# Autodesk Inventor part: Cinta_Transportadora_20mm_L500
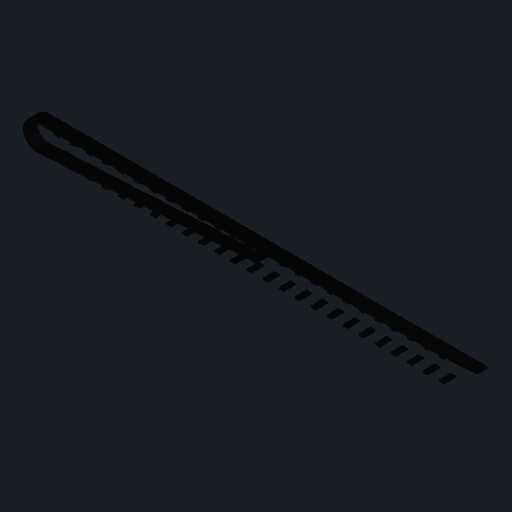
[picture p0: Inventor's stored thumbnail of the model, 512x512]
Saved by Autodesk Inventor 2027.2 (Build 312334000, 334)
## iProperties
Part Number: Cinta_Transportadora_20mm_L500
Material: Genérico
Document SubType Name: Modelado
Designer: Usuario
Appearance: Por defecto
Author: Usuario
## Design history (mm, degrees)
sketch "Boceto1"
  geometry: L1 (-220, 14)-(220, 14); L2 (220, 14)-(-220, -14); A1 r 14 centre (220, 0) between (220, -14) and (220, 14); A2 r 14 centre (-220, 0) between (-220, 14) and (-220, -14)
  constraints: 4 end point, 4 point on circle, 2 centre point
extrude "Extrusión1" new body sketch "Boceto1" stored distance "d0" = 12; taper "d1" = 0 deg
sketch "Boceto2"
  geometry: L1 (-220, 11.5)-(220, 11.5); L2 (220, 11.5)-(-220, -11.5); A1 r 11.5 centre (220, 0) between (220, -11.5) and (220, 11.5); A2 r 11.5 centre (-220, 0) between (-220, 11.5) and (-220, -11.5)
  constraints: 4 end point, 4 point on circle, 2 centre point
extrude "Extrusión2" cut sketch "Boceto2" stored distance "d2" = 12; taper "d3" = 0 deg
sketch "Boceto3"
  geometry: L1 (-202.5, -11.5)-(-197.5, -11.5); L2 (-197.5, -11.5)-(-197.5, -9.7); L3 (-197.5, -9.7)-(-202.5, -9.7); L4 (-202.5, -9.7)-(-202.5, -11.5); L5 (-202.5, 9.7)-(-197.5, 9.7); L6 (-197.5, 9.7)-(-197.5, 11.5); L7 (-197.5, 11.5)-(-202.5, 11.5); L8 (-202.5, 11.5)-(-202.5, 9.7); L9 (-186.5, -11.5)-(-181.5, -11.5); L10 (-181.5, -11.5)-(-181.5, -9.7); L11 (-181.5, -9.7)-(-186.5, -9.7); L12 (-186.5, -9.7)-(-186.5, -11.5); L13 (-186.5, 9.7)-(-181.5, 9.7); L14 (-181.5, 9.7)-(-181.5, 11.5); L15 (-181.5, 11.5)-(-186.5, 11.5); L16 (-186.5, 11.5)-(-186.5, 9.7); L17 (-170.5, -11.5)-(-165.5, -11.5); L18 (-165.5, -11.5)-(-165.5, -9.7); L19 (-165.5, -9.7)-(-170.5, -9.7); L20 (-170.5, -9.7)-(-170.5, -11.5); L21 (-170.5, 9.7)-(-165.5, 9.7); L22 (-165.5, 9.7)-(-165.5, 11.5); L23 (-165.5, 11.5)-(-170.5, 11.5); L24 (-170.5, 11.5)-(-170.5, 9.7); L25 (-154.5, -11.5)-(-149.5, -11.5); L26 (-149.5, -11.5)-(-149.5, -9.7); L27 (-149.5, -9.7)-(-154.5, -9.7); L28 (-154.5, -9.7)-(-154.5, -11.5); L29 (-154.5, 9.7)-(-149.5, 9.7); L30 (-149.5, 9.7)-(-149.5, 11.5); L31 (-149.5, 11.5)-(-154.5, 11.5); L32 (-154.5, 11.5)-(-154.5, 9.7); L33 (-138.5, -11.5)-(-133.5, -11.5); L34 (-133.5, -11.5)-(-133.5, -9.7); L35 (-133.5, -9.7)-(-138.5, -9.7); L36 (-138.5, -9.7)-(-138.5, -11.5); L37 (-138.5, 9.7)-(-133.5, 9.7); L38 (-133.5, 9.7)-(-133.5, 11.5); L39 (-133.5, 11.5)-(-138.5, 11.5); L40 (-138.5, 11.5)-(-138.5, 9.7); L41 (-122.5, -11.5)-(-117.5, -11.5); L42 (-117.5, -11.5)-(-117.5, -9.7); L43 (-117.5, -9.7)-(-122.5, -9.7); L44 (-122.5, -9.7)-(-122.5, -11.5); L45 (-122.5, 9.7)-(-117.5, 9.7); L46 (-117.5, 9.7)-(-117.5, 11.5); L47 (-117.5, 11.5)-(-122.5, 11.5); L48 (-122.5, 11.5)-(-122.5, 9.7); L49 (-106.5, -11.5)-(-101.5, -11.5); L50 (-101.5, -11.5)-(-101.5, -9.7); L51 (-101.5, -9.7)-(-106.5, -9.7); L52 (-106.5, -9.7)-(-106.5, -11.5); L53 (-106.5, 9.7)-(-101.5, 9.7); L54 (-101.5, 9.7)-(-101.5, 11.5); L55 (-101.5, 11.5)-(-106.5, 11.5); L56 (-106.5, 11.5)-(-106.5, 9.7); L57 (-90.5, -11.5)-(-85.5, -11.5); L58 (-85.5, -11.5)-(-85.5, -9.7); L59 (-85.5, -9.7)-(-90.5, -9.7); L60 (-90.5, -9.7)-(-90.5, -11.5); L61 (-90.5, 9.7)-(-85.5, 9.7); L62 (-85.5, 9.7)-(-85.5, 11.5); L63 (-85.5, 11.5)-(-90.5, 11.5); L64 (-90.5, 11.5)-(-90.5, 9.7)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
  constraints: 400 end point, 100 parallel, 50 horizontal, 50 perpendicular
extrude "Extrusión3" join sketch "Boceto3" stored distance "d4" = 12; taper "d5" = 0 deg
node "Sólido1"
node "Cuerpos sólidos"
node "Cuerpos de superficie"
